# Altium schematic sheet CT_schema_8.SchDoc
size 254 x 194 mm
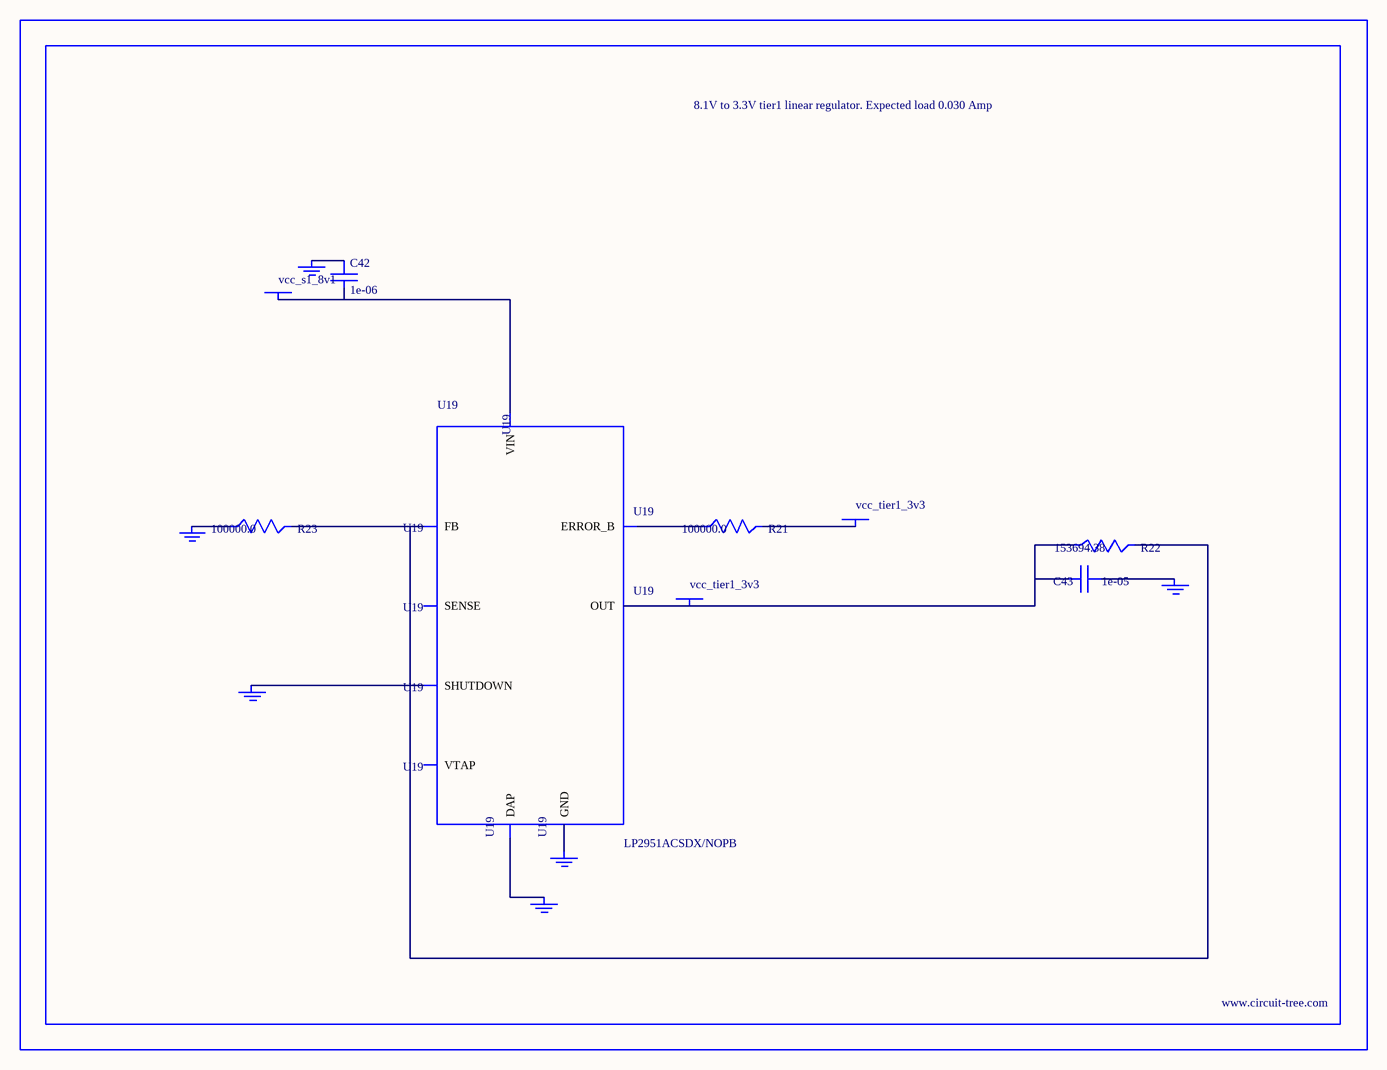
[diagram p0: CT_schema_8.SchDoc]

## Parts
BORDER7  (no value)
C42  1e-06  [C0603]
C43  1e-05  [C1210]
GND_INSTANCE_7_0  (no value)
GND_INSTANCE_7_1  (no value)
GND_INSTANCE_7_2  (no value)
GND_INSTANCE_7_3  (no value)
GND_INSTANCE_7_4  (no value)
GND_INSTANCE_7_5  (no value)
POWER_INSTANCE_7_0  vcc_tier1_3v3
POWER_INSTANCE_7_1  vcc_s1_8v1
POWER_INSTANCE_7_2  vcc_tier1_3v3
R21  100000.0  [R0603]
R22  153694.38  [R0603]
R23  100000.0  [R0603]
U19  LP2951ACSDX/NOPB  [WSON-8]

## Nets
NetC42_1: C42.1 GND_INSTANCE_7_3.0(GND)
NetC42_2: C42.2 POWER_INSTANCE_7_1.0(PWR) U19.8(VIN)
NetC43_1: C43.1 GND_INSTANCE_7_0.0(GND)
NetC43_2: C43.2 POWER_INSTANCE_7_2.0(PWR) R22.1 U19.1(OUT)
NetGND_INSTANCE_7_1_0: GND_INSTANCE_7_1.0(GND) U19.3(SHUTDOWN)
NetGND_INSTANCE_7_2_0: GND_INSTANCE_7_2.0(GND) R23.1
NetGND_INSTANCE_7_4_0: GND_INSTANCE_7_4.0(GND) U19.PAD(DAP)
NetGND_INSTANCE_7_5_0: GND_INSTANCE_7_5.0(GND) U19.4(GND)
NetPOWER_INSTANCE_7_0_0: POWER_INSTANCE_7_0.0(PWR) R21.2
NetR21_1: R21.1 U19.5(ERROR_B)
NetR22_2: R22.2 R23.2 U19.7(FB)

Not connected (* = marked no-connect by the designer): U19 2(SENSE) 6(VTAP)

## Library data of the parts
BORDER7 = BORDER_PAGE7
C42 = C0603C105K3RACTU
C43 = GRM32DR61E106MA12L
GND_INSTANCE_7_0-GND_INSTANCE_7_5 = GND
POWER_INSTANCE_7_0-POWER_INSTANCE_7_2 = PWR
R21 R23 = RC0603JR-07100KL
R22 = R22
